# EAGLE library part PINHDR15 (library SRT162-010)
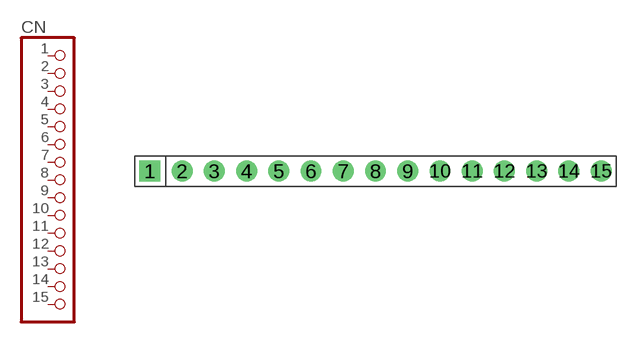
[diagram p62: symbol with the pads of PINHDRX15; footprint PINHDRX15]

Designator prefix CN

## PINHDR15  [PINHDRX15]
1  1  pas
2  2  pas
3  3  pas
4  4  pas
5  5  pas
6  6  pas
7  7  pas
8  8  pas
9  9  pas
10  10  pas
11  11  pas
12  12  pas
13  13  pas
14  14  pas
15  15  pas

## Footprint PINHDRX15 (pad centres in mm)
drill 1.1 square: 1 -17.78,0
drill 1.1 round: 2 -15.24,0; 3 -12.7,0; 4 -10.16,0; 5 -7.62,0; 6 -5.08,0; 7 -2.54,0; 8 0,0; 9 2.54,0; 10 5.08,0; 11 7.62,0; 12 10.16,0; 13 12.7,0; 14 15.24,0; 15 17.78,0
